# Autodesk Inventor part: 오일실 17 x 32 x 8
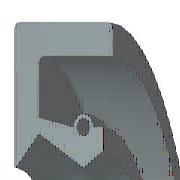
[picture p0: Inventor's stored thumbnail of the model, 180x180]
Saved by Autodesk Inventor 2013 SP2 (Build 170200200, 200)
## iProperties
IsCustomPart: 1
Created: 2012-02
Part Number: 오일실 17 x 32 x 8
Material: 고무
Description: 오일-실
Document SubType Name: Modeling
Standard: KS B 2804
Designer: mduedu
Standards Organization: KS
Language: ko-KR
Size Designation: D - 17 32 8
Categories: <MemberInstance><Categories><Category DisplayName="샤프트 부품" InternalName="7f7aeb1f-a693-4053-b835-cee3144e0d98" Mnemonic="SHFT"><Category DisplayName="실링" Intern
Density: 0.93 g/cm^3
Author: mduedu
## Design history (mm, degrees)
revolve "본체" stored, may be unused: angle "d17" = 90 deg
revolve "스프링1" stored, may be unused: angle "d18" = 90 deg
body "Solid1"
sketch "스케치1"
  geometry: L1 (0, 16)-(8, 16); L2 (8, 14.25)-(1.75, 14.25); L3 (1.75, 10.25)-(4.9, 8.5); L4 (4.9, 8.5)-(0, 8.5); L5 (0, 0)-(9.586, 0) reference; L6 (4.9, 8.5)-(6.3, 9.375); L7 (0, 18)-(0, -3) reference; L8 (-1.941, 0)-(11.507, 0) reference; L9 (4.2, 10.6)-(1.75, 11.21); L10 (1.75, 11.21)-(1.75, 14.25); L11 (0, 16)-(0, 8.588); L12 (4.9, 8.5)-(0, 8.5); L13 (1.75, 10.25)-(0.152, 8.528); L14 (8, 16)-(8, 14.25); L15 (5.6, 10.6)-(6.3, 10.6); L16 (6.3, 10.6)-(6.3, 9.375); C1 r 0.455 at (4.9, 10.6); A1 r 0.7 centre (4.9, 10.6) between (5.6, 10.6) and (4.2, 10.6); A2 r 0.088 centre (0.088, 8.588) between (0, 8.588) and (0.152, 8.528); 1 further point
  constraints: 28 end point, 5 horizontal alignment, 5 point on line, 4 point on circle, 4 vertical alignment, 3 centre point, 3 tangent, 2 collinear, 2 horizontal, 2 perpendicular, 1 coincident, 1 parallel
  dimensions: "d0" = 32 diameter of L1 L5 (= SD2); "d1" = 1.75 distance of L1.end L2.start (= SD); "d2" = 0.91 diameter of C1 (= SPDI); "d3" = 1.4 diameter of A1 (= SPDA); "d4" = 17 diameter of L3.end L5 (= NND); "d5" = 20.5 diameter of L3.start L5 (= TKDM); "d7" = 22.42 diameter of L9.end L5 (= TKDM + 0.24 x SWDT); "d8" = 1.75 distance between parallel lines of L11 L10 (= SD); "d9" = 4.9 distance from line of L11 C1.centre (= SPDST); "d10" = 21.2 diameter of C1.centre L5 (= HLDM); "d11" = 0.0875 radius of A2 (= 0.25 x LAB); "d12" = 6.3 distance between parallel lines of L11 L16 (= SDI); "d13" = 18.75 diameter of L6.end L5 (= ABDM); "d14" = 8 distance from line of L11 L1.end (= SWDT)
fillet "모깎기1" dims "d6" = 0.3 (= RR)
other parameters: "SD2" = 32 [user parameter; used in 1 equation term], "SWDT" = 8 [user parameter; used in 2 equation terms], "RR" = 0.3 [user parameter; used in 1 equation term], "SD" = 1.75 [user parameter; used in 2 equation terms], "NND" = 17 [user parameter; used in 1 equation term], "SPDA" = 1.4 [user parameter; used in 1 equation term], "SPDI" = 0.91 [user parameter; used in 1 equation term], "TKDM" = 20.5 [user parameter; used in 2 equation terms], "HLDM" = 21.2 [user parameter; used in 1 equation term], "ABDM" = 18.75 [user parameter; used in 1 equation term], "SDI" = 6.3 [user parameter; used in 1 equation term], "SPDST" = 4.9 [user parameter; used in 1 equation term], "LAB" = 0.35 [user parameter; used in 1 equation term], "d15" = 0, "d16" = 0, "d19" = 0
